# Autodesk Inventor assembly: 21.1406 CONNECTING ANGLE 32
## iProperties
Created: 2007-01
Part Number: 21.1406 CONNECTING ANGLE 32
Document SubType Name: Assembly
Designer: Andy Moles
Author: Andy Moles
